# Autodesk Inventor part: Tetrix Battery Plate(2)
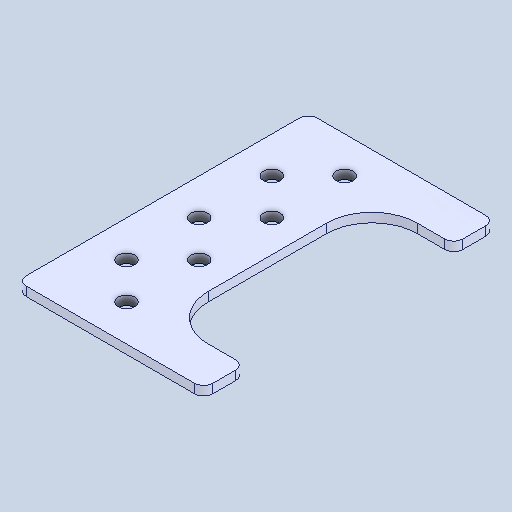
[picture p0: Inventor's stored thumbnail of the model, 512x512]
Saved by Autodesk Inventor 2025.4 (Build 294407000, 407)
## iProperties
Created: 2021-10
Part Number: Tetrix Battery Plate(2)
Material: Genérico
Document SubType Name: Modeling
Designer: usuario
Density: 1 g/cm^3
Appearance: Valor por defecto
Author: usuario
Sending System: SolidWorks 2016
Last Author: LENOVO
Last Saved: 2021-10-21
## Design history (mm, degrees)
feature "Boss-Extrude1"
node "Plane1"
node "Sólido1"
